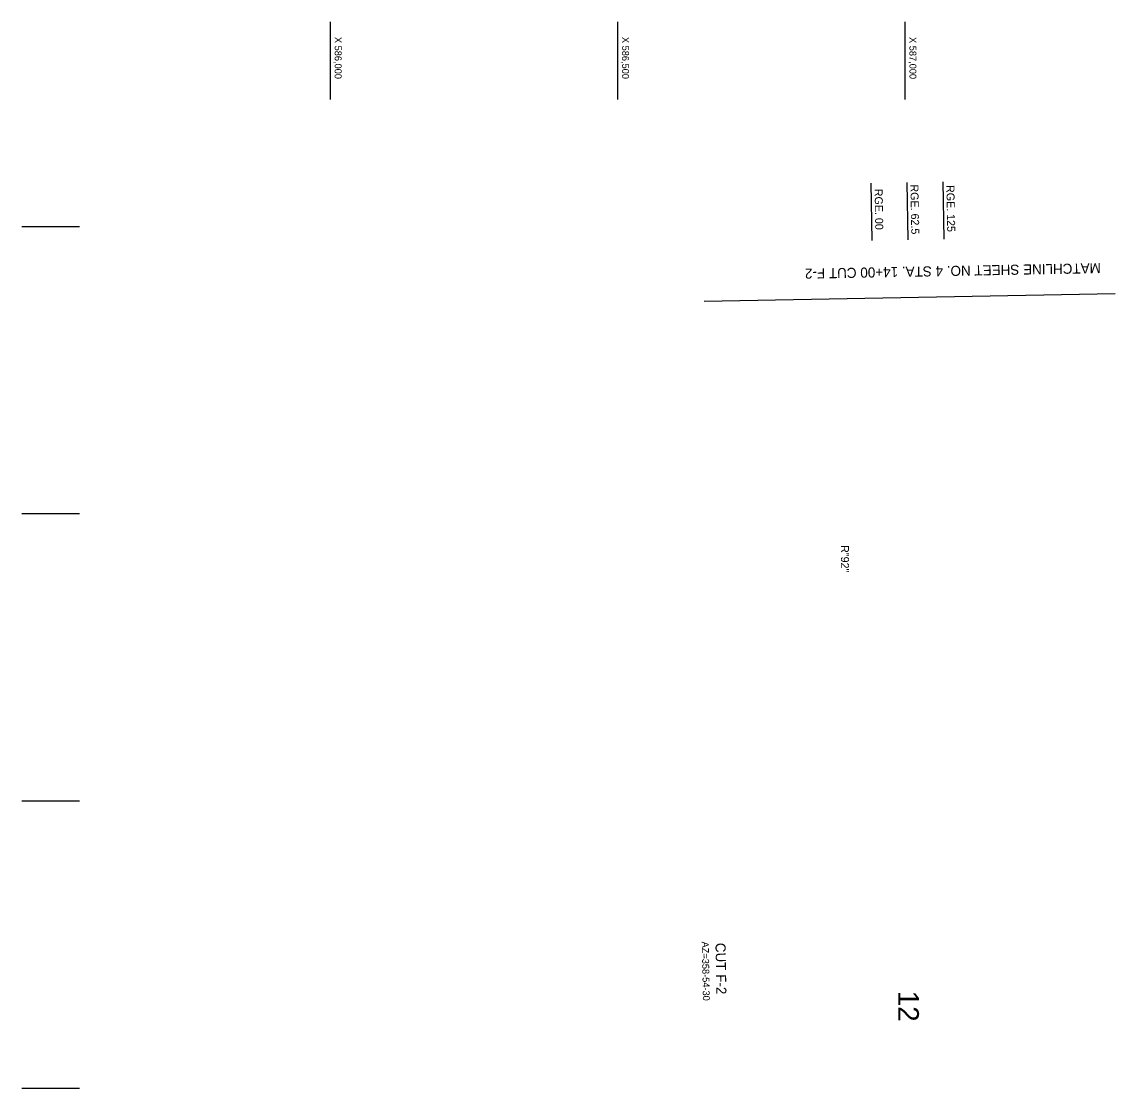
# Model space of a CAD drawing. Extents: x 585414 to 588664, y 1932755 to 1936856.
# Drawn here: x 585464 to 587366, y 1935000 to 1936856 of the extents above; entities that cross this region are included whole.
import ezdxf

# ---------------------------------------------------------------- set-up
doc = ezdxf.new("R2010")
doc.units = 0
for name, color, linetype in [('V-ANNO-KEYN', 7, 'Continuous'), ('V-ANNO-MASK', 7, 'Continuous'), ('V-ANNO-SYMB', 7, 'Continuous'), ('V-ANNO-TEXT', 7, 'Continuous'), ('V-DUCT-MULT', 7, 'Continuous'), ('V-DUCT-MULT-IDEN', 7, 'Continuous')]:
    doc.layers.add(name, color=color, linetype=linetype)

msp = doc.modelspace()

# ---------------------------------------------------------------- linework, layer by layer
at = {"layer": 'V-ANNO-KEYN'}
for p, q in [((586000, 1936855.9), (586000, 1936720.9)), ((586500, 1936855.9), (586500, 1936720.9)), ((587000, 1936855.9), (587000, 1936720.9)), ((585463.7, 1936500), (585563.7, 1936500)), ((585463.7, 1936000), (585563.7, 1936000)), ((585463.7, 1935500), (585563.7, 1935500)), ((585463.7, 1935000), (585563.7, 1935000))]:
    msp.add_line(p, q, dxfattribs=at)
at = {"layer": 'V-ANNO-SYMB'}
for p, q in [((586940.9, 1936575.3), (586942.8, 1936475.3)), ((587003.4, 1936576.5), (587005.3, 1936476.5)), ((587065.9, 1936577.7), (587067.8, 1936477.7))]:
    msp.add_line(p, q, dxfattribs=at)
at = {"layer": 'V-DUCT-MULT'}
msp.add_line((586650.6, 1936369.7), (587365.8, 1936383.4), dxfattribs=at)

# ---------------------------------------------------------------- texts
at = {"layer": 'V-ANNO-MASK'}
for s, p in [('X 586,000', (586008, 1936829.7)), ('X 586,500', (586508, 1936829.7)), ('X 587,000', (587008, 1936829.5))]:
    msp.add_text(s, height=12, rotation=270, dxfattribs=at).set_placement(p)
at = {"layer": 'V-ANNO-SYMB'}
for s, height, rotation, p in [('RGE. 00', 13.92, 271.0918, (586947.2, 1936565.2)), ('RGE. 62.5', 13.92, 271.0918, (587009.6, 1936572.8)), ('RGE. 125', 13.92, 271.0918, (587072.2, 1936571.8)), ('R"92"', 13.92, 270, (586888.8, 1935945.2)), ('12', 36, 270, (586988.4, 1935169.4))]:
    msp.add_text(s, height=height, rotation=rotation, dxfattribs=at).set_placement(p)
at = {"layer": 'V-ANNO-TEXT'}
msp.add_text('MATCHLINE SHEET NO. 4 STA. 14+00 CUT F-2', height=17.52, rotation=181.0918, dxfattribs=at).set_placement((587340.8, 1936436.1))
at = {"layer": 'V-DUCT-MULT-IDEN'}
for s, height, p in [('AZ=358-54-30', 12, (586646.7, 1935255)), ('CUT F-2', 17.52, (586670.4, 1935252.8))]:
    msp.add_text(s, height=height, rotation=271.0918, dxfattribs=at).set_placement(p)

doc.saveas('drawing.dxf')
